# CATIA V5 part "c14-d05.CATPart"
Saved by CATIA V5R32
Part number: Part1
Bounding box of the stored display mesh (mm): x -55 to 55, y -96.632 to 96.632, z -25 to 65
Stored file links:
  D:\PROJECTS\Project 2022\CATIA V5 6R 2022\Resources\Part Files\c14_catia_v5_6r2022_prt\c14-catia-v5-6r2022-figr-14-18\c14-d05.CATPart
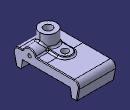
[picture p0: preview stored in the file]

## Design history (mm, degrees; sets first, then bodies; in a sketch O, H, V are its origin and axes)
Body1 (main body)
  Sketch1 on yz-plane, origin (0, 0, 0), H (0, 0, -1), V (0, 1, 0)
    construction line L1 (-49.4514, 0) -> (56.6299, 0)
    line L2 (0, 0) -> (0, 70.5918)
    point P3 (25, 75)
    line L3 (25, 75) -> (25, 90)
    point P4 (25, 90)
    line L4 (25, 90) -> (-25, 100)
    point P5 (-25, 100)
    line L5 (-25, 100) -> (-25, 0)
    point P6 (-25, 0)
    point P7 (0, 0)
    construction line L6 through (0, 0) direction (-1, 0)
    point P10 (25, -75)
    point P11 (25, -90)
    point P12 (-25, -100)
    point P13 (-25, 0)
    line L7 (0, 0) -> (0, -70.5918)
    line L8 (25, -75) -> (25, -90)
    line L9 (25, -90) -> (-25, -100)
    line L10 (-25, -100) -> (-25, 0)
    line L11 (25, 75) -> (0, 70.5918)
    point P14 (0, 70.5918)
    point P15 (0, -70.5918)
    point P16 (25, -75)
    line L12 (25, -75) -> (0, -70.5918)
    axis line L13 (25, 75) -> (-31.7388, 75)
    distance P5 P12 = 200
    length L3 = 15
    angle L11 L13 = 10
    distance L3 L5 = 50
    distance P3 P10 = 150
    angle L5 L6 = 270 (reference)
    coincidence: P6 L1, O P7, P6 P13, P10 P16
    symmetry: O P7 L1, P3 P10 L1, P4 P11 L1, P5 P12 L1, P6 P13 L1, L2 L7 L1, L3 L8 L1, L4 L9 L1, L5 L10 L1, P14 P15 L1, P3 P16 L1, L11 L12 L1
  Pad1: profile Sketch1, direction (1, 0, 0), length 55, mirrored extent
  Sketch2 on face of Pad1, origin (55, 0, 0), H (0, 1, 0), V (0, 0, 1)
    arc A1 centre (-50, 20) radius 20 from (-30.6351, 25) to (-69.3649, 25) ccw
    point P1 (-50, 20)
    line L1 (-69.3649, 25) -> (-30.6351, 25)
    reference projected line E1 (0, 25) -> (-100, 25) from edge [face of Pad1 | face of Pad1]
    reference projected point E2 (-100, 25) from vertex [face of Pad1 | face of Pad1 | face of Pad1]
    reference projected line E3 (0, 25) -> (-100, 25) from edge [face of Pad1 | face of Pad1]
    radius A1 = 20
    distance P1 E2 H = 50
    distance P1 E3 = 5
    horizontal: L1 H
    coincidence: L1 E1
  Pad2: profile Sketch2, direction (-1, 0, 0), length 55
  Sketch3 on face of Pad1, origin (0, 0, 25), H (1, 0, 0), V (0, 1, 0)
    circle A1 centre (0, -50) radius 25
    point P1 (0, -50)
    point P2 (0, -25)
    radius A1 = 25
    distance P1 H = 50
    coincidence: P1 V, A1 P2, P2 V
  Pad3: profile Sketch3, direction (0, 0, 1), length 40
  Sketch4 on face of Pad1, origin (0, 0, 25), H (1, 0, 0), V (0, 1, 0)
    line L1 (-20, -50) -> (-20, 0)
    point P2 (-20, 0)
    arc A1 centre (0, 0) radius 20 from (-20, 0) to (20, 0) cw
    point P3 (0, 0)
    line L2 (20, 0) -> (20, -50)
    line L3 (20, -50) -> (-20, -50)
    distance P3 L3 = 50
    radius A1 = 20
    coincidence: P2 H, P3 O
    vertical: L1 V, L2 V
    tangency: A1 L1, L2 A1
    horizontal: L3 H
  Pad4: profile Sketch4, direction (0, 0, 1), length 5
  Fillet1: radius 15, on edge [face of Pad1 | face of Pad1] (x2)
  Fillet2: radius 5, on edge [face of Pad1 | face of Pad4]
  Fillet3: radius 2, on edge [face of Pad4 | face of Fillet2]
  Fillet4: radius 5, on edge [face of Pad1 | face of Pad2]
  Fillet5: radius 5, on edge [face of Pad2 | face of Pad1]
  Fillet6: radius 5, on edge [face of Pad2 | face of Pad3]
  Fillet7: radius 2, on edge [face of Pad1 | face of Fillet1]; 1 edge
  Sketch5 on face of Pad1, origin (55, -45.7053, 34.0838), H (0, 1, 0), V (0, 0, 1)
    point P1 (-4.2947, -14.0838)
    reference projected arc E1 centre (-4.2947, -14.0838) radius 20 from (15.0702, -9.0838) to (-23.6596, -9.0838) ccw from edge of Pad2
    concentricity: P1 E1
  Hole1: placed by Sketch5, at (55, -50, 20) direction (-1, 0, 0), diameter 10, depth 20
  Sketch6 on face of Pad3, origin (0, -50, 65), H (1, 0, 0), V (0, 1, 0)
    point P1 (0, 0)
    reference projected circle E1 centre (0, 0) radius 25 from edge [face of Pad3 | face of Pad3]
    concentricity: P1 E1
  Hole2: placed by Sketch6, at (0, -50, 65) direction (0, 0, -1), diameter 25, through (limit type 3)
  Sketch7 on face of Pad4, origin (-2.136, -9.3115, 30), H (1, 0, 0), V (0, 1, 0)
    point P1 (2.136, 9.3115)
    reference projected arc E1 centre (2.136, 9.3115) radius 18.2918 from (20.4278, 9.3115) to (-16.1558, 9.3115) ccw from edge [face of Pad4 | face of Fillet3]
    concentricity: P1 E1
  Hole3: placed by Sketch7, at (0, 0, 30) direction (0, 0, -1), diameter 20, through (limit type 3)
